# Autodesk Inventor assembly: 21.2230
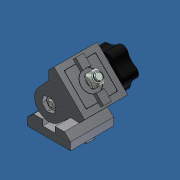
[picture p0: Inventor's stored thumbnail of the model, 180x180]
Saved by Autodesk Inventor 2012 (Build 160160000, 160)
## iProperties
Created: 2007-01
Part Number: 21.2230
Document SubType Name: Assembly
Designer: Andy Moles
Description: ANGLE BRACKET R FIXABLE
Author: Andy Moles
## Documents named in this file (8)
- C:\Andys Backup Data\ANDY'S INVENTOR\INVENTOR LIBRARIES\PARTS LIBRARY\LINKS AND HINGES\21.2230 ANGLE BRACKET R FIXABLE.iam
- C:\Andys Backup Data\ANDY'S INVENTOR\INVENTOR LIBRARIES\PARTS LIBRARY\LINKS AND HINGES\SUBCOMPONENTS\21.2042 ANGLE BRACKET R AL BLOCK.ipt
- C:\Andys Backup Data\ANDY'S INVENTOR\INVENTOR LIBRARIES\PARTS LIBRARY\FASTENING ELEMENTS\NUTS\21.1526 M8 HEX NUT.ipt
- C:\Andys Backup Data\ANDY'S INVENTOR\INVENTOR LIBRARIES\PARTS LIBRARY\FASTENING ELEMENTS\SUBCOMPONENTS\21.2016 ANTI TWIST.ipt
- C:\Andys Backup Data\ANDY'S INVENTOR\INVENTOR LIBRARIES\PARTS LIBRARY\FASTENING ELEMENTS\SCREWS CAP\21.1202 M8X20.ipt
- C:\Andys Backup Data\ANDY'S INVENTOR\INVENTOR LIBRARIES\PARTS LIBRARY\FASTENING ELEMENTS\NUTS\21.1351 M8 SQUARE NUT.ipt
- C:\Andys Backup Data\ANDY'S INVENTOR\INVENTOR LIBRARIES\PARTS LIBRARY\LINKS AND HINGES\SUBCOMPONENTS\21.2230 THREADED HANDKNOB.ipt
- C:\Andys Backup Data\ANDY'S INVENTOR\INVENTOR LIBRARIES\PARTS LIBRARY\FASTENING ELEMENTS\WASHERS\21.1123 M8 ROUND O.D. 20mm.ipt
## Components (11 placed, 7 different names)
1. 21.2042 ANGLE BRACKET R AL BLOCK:1 — Mate:1, Mate:2, Flush:1, Insert:3, Insert:7, Mate:10, Mate:12, Mate:13, Mate:14
2. 21.2042 ANGLE BRACKET R AL BLOCK:2 — Insert:1, Angle:2, Insert:4, Insert:6, Mate:8, Mate:14
3. 21.1526 M8 HEX NUT:1 — Insert:1, Angle:2
4. ANTI-ROTATION DEVICE:1 — Insert:4
5. ANTI-ROTATION DEVICE:2 — Insert:3
6. 21.1202  M8 x 20:1 — Insert:6, Mate:7, Mate:11
7. 21.1202  M8 x 20:2 — Insert:7, Mate:9
8. 21.1351 M8 SQUARE NUT:1 — Mate:7, Mate:8
9. 21.1351 M8 SQUARE NUT:2 — Mate:9, Mate:10
10. 21.2230 THREADED HANDKNOB:1 — Insert:8, Mate:12
11. 21.1123 M8 ROUND O.D. 20mm:1 — Insert:8, Mate:13
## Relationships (18: Mate 10, Insert 6, Flush 1, Angle 1)
- Mate:1: 21.2042 ANGLE BRACKET R AL BLOCK:1
- Mate:2: 21.2042 ANGLE BRACKET R AL BLOCK:1
- Flush:1: 21.2042 ANGLE BRACKET R AL BLOCK:1
- Insert:1: 21.2042 ANGLE BRACKET R AL BLOCK:2 ↔ 21.1526 M8 HEX NUT:1
- Angle:2: 21.2042 ANGLE BRACKET R AL BLOCK:2 ↔ 21.1526 M8 HEX NUT:1
- Insert:3: 21.2042 ANGLE BRACKET R AL BLOCK:1 ↔ ANTI-ROTATION DEVICE:2
- Insert:4: 21.2042 ANGLE BRACKET R AL BLOCK:2 ↔ ANTI-ROTATION DEVICE:1
- Insert:6: 21.2042 ANGLE BRACKET R AL BLOCK:2 ↔ 21.1202  M8 x 20:1
- Insert:7: 21.2042 ANGLE BRACKET R AL BLOCK:1 ↔ 21.1202  M8 x 20:2
- Mate:7: 21.1202  M8 x 20:1 ↔ 21.1351 M8 SQUARE NUT:1
- Mate:8: 21.2042 ANGLE BRACKET R AL BLOCK:2 ↔ 21.1351 M8 SQUARE NUT:1
- Mate:9: 21.1202  M8 x 20:2 ↔ 21.1351 M8 SQUARE NUT:2
- Mate:10: 21.2042 ANGLE BRACKET R AL BLOCK:1 ↔ 21.1351 M8 SQUARE NUT:2
- Mate:11: 21.1202  M8 x 20:1
- Insert:8: 21.2230 THREADED HANDKNOB:1 ↔ 21.1123 M8 ROUND O.D. 20mm:1
- Mate:12: 21.2042 ANGLE BRACKET R AL BLOCK:1 ↔ 21.2230 THREADED HANDKNOB:1
- Mate:13: 21.2042 ANGLE BRACKET R AL BLOCK:1 ↔ 21.1123 M8 ROUND O.D. 20mm:1
- Mate:14: 21.2042 ANGLE BRACKET R AL BLOCK:1 ↔ 21.2042 ANGLE BRACKET R AL BLOCK:2
